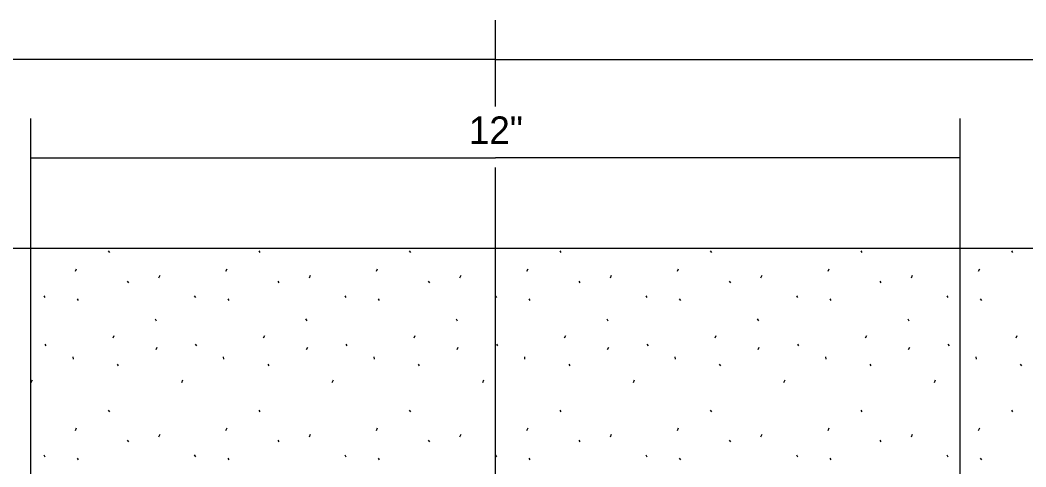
# Model space of a CAD drawing. Extents: x 99988 to 100172, y 99995 to 100047.
# Drawn here: x 100001.615 to 100004.171, y 100007.558 to 100008.694 of the extents above; entities that cross this region are included whole.
import ezdxf

# ---------------------------------------------------------------- set-up
doc = ezdxf.new("R2010")
doc.units = 0
for name, color, linetype in [('Level 1', 7, 'Continuous'), ('Level 15', 7, 'Continuous'), ('Level 20', 7, 'Continuous'), ('Level 3', 7, 'Continuous')]:
    doc.layers.add(name, color=color, linetype=linetype)

msp = doc.modelspace()

# ---------------------------------------------------------------- linework, layer by layer
at = {"layer": 'Level 1'}
msp.add_line((100000.585, 100008.1139), (100009.7707, 100008.1139), dxfattribs=at)
at = {"layer": 'Level 15'}
for p, q in [((100002.8228, 100008.4739), (100002.8228, 100008.6939)), ((100002.8228, 100008.5939), (100000.585, 100008.5939)), ((100002.8228, 100008.5939), (100005.1851, 100008.5939)), ((100001.6417, 100007.3958), (100001.6417, 100008.4439)), ((100004.004, 100007.3958), (100004.004, 100008.4439)), ((100001.6417, 100008.3439), (100002.8228, 100008.3439)), ((100004.004, 100008.3439), (100002.8228, 100008.3439)), ((100002.8228, 100006.9869), (100002.8228, 100008.3189))]:
    msp.add_line(p, q, dxfattribs=at)
at = {"layer": 'Level 3'}
for p, q in [((100001.8386, 100008.1069), (100001.8415, 100008.1026)), ((100002.2213, 100008.1069), (100002.2242, 100008.1026)), ((100002.6039, 100008.1069), (100002.6068, 100008.1026)), ((100002.9866, 100008.1069), (100002.9894, 100008.1026)), ((100003.3692, 100008.1069), (100003.3721, 100008.1026)), ((100003.7518, 100008.1069), (100003.7547, 100008.1026)), ((100004.1345, 100008.1069), (100004.1374, 100008.1026)), ((100001.7552, 100008.0553), (100001.7581, 100008.0617)), ((100002.1379, 100008.0553), (100002.1408, 100008.0617)), ((100002.5205, 100008.0553), (100002.5234, 100008.0617)), ((100002.9032, 100008.0553), (100002.906, 100008.0617)), ((100003.2858, 100008.0553), (100003.2887, 100008.0617)), ((100003.6684, 100008.0553), (100003.6713, 100008.0617)), ((100004.0511, 100008.0553), (100004.054, 100008.0617)), ((100001.8869, 100008.0303), (100001.8898, 100008.026)), ((100001.9674, 100008.0387), (100001.9703, 100008.0452)), ((100002.2695, 100008.0303), (100002.2724, 100008.026)), ((100002.35, 100008.0387), (100002.3529, 100008.0452)), ((100002.6522, 100008.0303), (100002.6551, 100008.026)), ((100002.7327, 100008.0387), (100002.7356, 100008.0452)), ((100003.0348, 100008.0303), (100003.0377, 100008.026)), ((100003.1153, 100008.0387), (100003.1182, 100008.0452)), ((100003.4175, 100008.0303), (100003.4203, 100008.026)), ((100003.498, 100008.0387), (100003.5008, 100008.0452)), ((100003.8001, 100008.0303), (100003.803, 100008.026)), ((100003.8806, 100008.0387), (100003.8835, 100008.0452)), ((100001.6747, 100007.9927), (100001.6776, 100007.9884)), ((100001.7597, 100007.9849), (100001.7626, 100007.9806)), ((100002.0573, 100007.9927), (100002.0602, 100007.9884)), ((100002.1423, 100007.9849), (100002.1452, 100007.9806)), ((100002.44, 100007.9927), (100002.4428, 100007.9884)), ((100002.525, 100007.9849), (100002.5278, 100007.9806)), ((100002.8226, 100007.9927), (100002.8255, 100007.9884)), ((100002.9076, 100007.9849), (100002.9105, 100007.9806)), ((100003.2052, 100007.9927), (100003.2081, 100007.9884)), ((100003.2902, 100007.9849), (100003.2931, 100007.9806)), ((100003.5879, 100007.9927), (100003.5908, 100007.9884)), ((100003.6729, 100007.9849), (100003.6758, 100007.9806)), ((100003.9705, 100007.9927), (100003.9734, 100007.9884)), ((100004.0555, 100007.9849), (100004.0584, 100007.9806)), ((100001.9578, 100007.9338), (100001.9607, 100007.9295)), ((100002.3405, 100007.9338), (100002.3434, 100007.9295)), ((100002.7231, 100007.9338), (100002.726, 100007.9295)), ((100003.1058, 100007.9338), (100003.1086, 100007.9295)), ((100003.4884, 100007.9338), (100003.4913, 100007.9295)), ((100003.871, 100007.9338), (100003.8739, 100007.9295)), ((100001.8509, 100007.8855), (100001.8538, 100007.892)), ((100002.2335, 100007.8855), (100002.2364, 100007.892)), ((100002.6162, 100007.8855), (100002.619, 100007.892)), ((100002.9988, 100007.8855), (100003.0017, 100007.892)), ((100003.3814, 100007.8855), (100003.3843, 100007.892)), ((100003.7641, 100007.8855), (100003.767, 100007.892)), ((100004.1467, 100007.8855), (100004.1496, 100007.892)), ((100001.6774, 100007.87), (100001.6803, 100007.8656)), ((100001.9602, 100007.856), (100001.9631, 100007.8625)), ((100002.06, 100007.87), (100002.0629, 100007.8656)), ((100002.3429, 100007.856), (100002.3457, 100007.8625)), ((100002.4427, 100007.87), (100002.4455, 100007.8656)), ((100002.7255, 100007.856), (100002.7284, 100007.8625)), ((100002.8253, 100007.87), (100002.8282, 100007.8656)), ((100003.1081, 100007.856), (100003.111, 100007.8625)), ((100003.2079, 100007.87), (100003.2108, 100007.8656)), ((100003.4908, 100007.856), (100003.4937, 100007.8625)), ((100003.5906, 100007.87), (100003.5935, 100007.8656)), ((100003.8734, 100007.856), (100003.8763, 100007.8625)), ((100003.9732, 100007.87), (100003.9761, 100007.8656)), ((100001.7486, 100007.8379), (100001.7493, 100007.8315)), ((100002.1312, 100007.8379), (100002.1319, 100007.8315)), ((100002.5139, 100007.8379), (100002.5146, 100007.8315)), ((100002.8965, 100007.8379), (100002.8972, 100007.8315)), ((100003.2791, 100007.8379), (100003.2799, 100007.8315)), ((100003.6618, 100007.8379), (100003.6625, 100007.8315)), ((100004.0444, 100007.8379), (100004.0451, 100007.8315)), ((100001.8614, 100007.8189), (100001.8642, 100007.8146)), ((100002.244, 100007.8189), (100002.2469, 100007.8146)), ((100002.6266, 100007.8189), (100002.6295, 100007.8146)), ((100003.0093, 100007.8189), (100003.0121, 100007.8146)), ((100003.3919, 100007.8189), (100003.3948, 100007.8146)), ((100003.7746, 100007.8189), (100003.7774, 100007.8146)), ((100004.1572, 100007.8189), (100004.1601, 100007.8146)), ((100001.643, 100007.7726), (100001.6459, 100007.779)), ((100002.0257, 100007.7726), (100002.0286, 100007.779)), ((100002.4083, 100007.7726), (100002.4112, 100007.779)), ((100002.791, 100007.7726), (100002.7938, 100007.779)), ((100003.1736, 100007.7726), (100003.1765, 100007.779)), ((100003.5562, 100007.7726), (100003.5591, 100007.779)), ((100003.9389, 100007.7726), (100003.9418, 100007.779)), ((100001.8386, 100007.7022), (100001.8415, 100007.6979)), ((100002.2213, 100007.7022), (100002.2242, 100007.6979)), ((100002.6039, 100007.7022), (100002.6068, 100007.6979)), ((100002.9866, 100007.7022), (100002.9894, 100007.6979)), ((100003.3692, 100007.7022), (100003.3721, 100007.6979)), ((100003.7518, 100007.7022), (100003.7547, 100007.6979)), ((100004.1345, 100007.7022), (100004.1374, 100007.6979)), ((100001.7552, 100007.6505), (100001.7581, 100007.657)), ((100001.9674, 100007.634), (100001.9703, 100007.6405)), ((100002.1379, 100007.6505), (100002.1408, 100007.657)), ((100002.35, 100007.634), (100002.3529, 100007.6405)), ((100002.5205, 100007.6505), (100002.5234, 100007.657)), ((100002.7327, 100007.634), (100002.7356, 100007.6405)), ((100002.9032, 100007.6505), (100002.906, 100007.657)), ((100003.1153, 100007.634), (100003.1182, 100007.6405)), ((100003.2858, 100007.6505), (100003.2887, 100007.657)), ((100003.498, 100007.634), (100003.5008, 100007.6405)), ((100003.6684, 100007.6505), (100003.6713, 100007.657)), ((100003.8806, 100007.634), (100003.8835, 100007.6405)), ((100004.0511, 100007.6505), (100004.054, 100007.657)), ((100001.8869, 100007.6256), (100001.8898, 100007.6213)), ((100002.2695, 100007.6256), (100002.2724, 100007.6213)), ((100002.6522, 100007.6256), (100002.6551, 100007.6213)), ((100003.0348, 100007.6256), (100003.0377, 100007.6213)), ((100003.4175, 100007.6256), (100003.4203, 100007.6213)), ((100003.8001, 100007.6256), (100003.803, 100007.6213)), ((100001.6747, 100007.588), (100001.6776, 100007.5836)), ((100001.7597, 100007.5802), (100001.7626, 100007.5759)), ((100002.0573, 100007.588), (100002.0602, 100007.5836)), ((100002.1423, 100007.5802), (100002.1452, 100007.5759)), ((100002.44, 100007.588), (100002.4428, 100007.5836)), ((100002.525, 100007.5802), (100002.5278, 100007.5759)), ((100002.8226, 100007.588), (100002.8255, 100007.5836)), ((100002.9076, 100007.5802), (100002.9105, 100007.5759)), ((100003.2052, 100007.588), (100003.2081, 100007.5836)), ((100003.2902, 100007.5802), (100003.2931, 100007.5759)), ((100003.5879, 100007.588), (100003.5908, 100007.5836)), ((100003.6729, 100007.5802), (100003.6758, 100007.5759)), ((100003.9705, 100007.588), (100003.9734, 100007.5836)), ((100004.0555, 100007.5802), (100004.0584, 100007.5759))]:
    msp.add_line(p, q, dxfattribs=at)

# ---------------------------------------------------------------- texts
at = {"layer": 'Level 20'}
msp.add_text('12"', height=0.07, dxfattribs=at).set_placement((100002.7554, 100008.3789))

doc.saveas('drawing.dxf')
